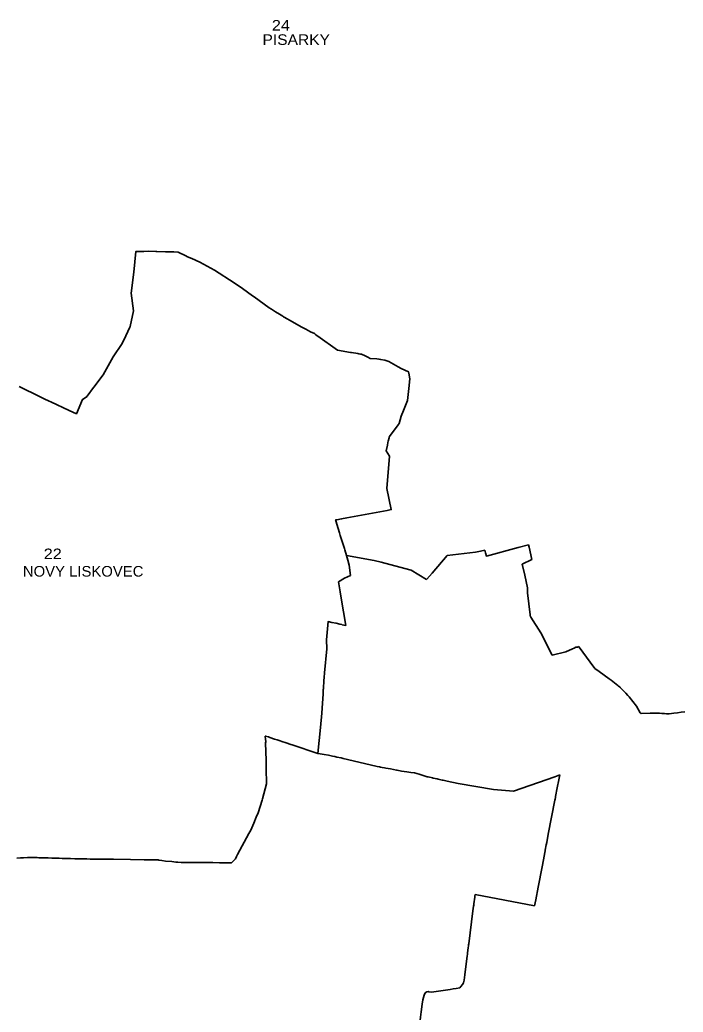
# Model space of a CAD drawing. Extents: x -610940 to -588976, y -1170376 to -1149800.
# Drawn here: x -602206 to -600639, y -1163066 to -1160722 of the extents above; entities that cross this region are included whole.
import ezdxf

# ---------------------------------------------------------------- set-up
doc = ezdxf.new("R2010")
doc.units = 0
doc.header["$LTSCALE"] = 10
doc.layers.add('54', color=7, linetype='Continuous', lineweight=35)
doc.layers.add('55', color=7, linetype='Continuous')
doc.layers.add('56', color=7, linetype='Continuous')

msp = doc.modelspace()

# ---------------------------------------------------------------- linework, layer by layer
at = {"layer": '54'}
for p, q in [((-601028.66, -1161968.5), (-601004.38, -1161961.9)), ((-601004.38, -1161961.9), (-601002.71, -1161967.82)), ((-601433.83, -1161987.17), (-601432.39, -1161993.01)), ((-601433.83, -1161987.17), (-601368.49, -1161999.15)), ((-601232.03, -1162028.94), (-601196.39, -1161987.52)), ((-601196.39, -1161987.52), (-601129.57, -1161979.71)), ((-601129.57, -1161979.71), (-601121.83, -1161978.16)), ((-601121.83, -1161978.16), (-601110.37, -1161975.86)), ((-601110.37, -1161975.86), (-601107.13, -1161975.2)), ((-601002.71, -1161967.82), (-600996.22, -1161996.64)), ((-601368.49, -1161999.15), (-601351.89, -1162003.59)), ((-601351.89, -1162003.59), (-601284.54, -1162021.25)), ((-601018.85, -1162007.88), (-600996.22, -1161996.64)), ((-601018.85, -1162007.88), (-601012.85, -1162033.72)), ((-601012.85, -1162033.72), (-601006.89, -1162063.9)), ((-601453.33, -1162049.5), (-601439.28, -1162040.88)), ((-601453.33, -1162049.5), (-601449.23, -1162073.15)), ((-601006.89, -1162075.78), (-601006.89, -1162063.9)), ((-601006.89, -1162075.78), (-601000.04, -1162127.57)), ((-601458.84, -1162147.68), (-601450.18, -1162149.59)), ((-601450.18, -1162149.59), (-601445.12, -1162150.7)), ((-600998.81, -1162133.13), (-600975.07, -1162170.16)), ((-600975.07, -1162170.16), (-600948.1, -1162222.9)), ((-601481.32, -1162186.65), (-601480.67, -1162207.93)), ((-601486.34, -1162264.83), (-601480.67, -1162207.93)), ((-600948.1, -1162222.9), (-600915.57, -1162215.22)), ((-600915.57, -1162215.22), (-600899.9, -1162207.82)), ((-600899.9, -1162207.82), (-600896.12, -1162206.03)), ((-600896.12, -1162206.03), (-600892.44, -1162204.3)), ((-600892.44, -1162204.3), (-600891.58, -1162203.89)), ((-600891.58, -1162203.89), (-600888.68, -1162203.69)), ((-600858.69, -1162239.36), (-600847.41, -1162254.38)), ((-601487.07, -1162275.64), (-601486.34, -1162264.83)), ((-600847.41, -1162254.38), (-600837.2, -1162261.68)), ((-600837.2, -1162261.68), (-600813.38, -1162278.94)), ((-601487.71, -1162283.88), (-601487.57, -1162281.75)), ((-601487.57, -1162281.75), (-601487.12, -1162276.48)), ((-601487.12, -1162276.48), (-601487.07, -1162275.64)), ((-600813.38, -1162278.94), (-600809.01, -1162282.2)), ((-600809.01, -1162282.2), (-600793.34, -1162294.33)), ((-601488.96, -1162303.8), (-601488.86, -1162302.06)), ((-601488.86, -1162302.06), (-601488.43, -1162295.92)), ((-600793.34, -1162294.33), (-600791.32, -1162295.92)), ((-600791.32, -1162295.92), (-600787.77, -1162298.7)), ((-600778.35, -1162308.57), (-600774.52, -1162312.51)), ((-600774.52, -1162312.51), (-600769.1, -1162318.27)), ((-600769.1, -1162318.27), (-600766.14, -1162321.31)), ((-600766.14, -1162321.31), (-600749.15, -1162343.17)), ((-600749.15, -1162343.17), (-600740.6, -1162359.47)), ((-600740.6, -1162359.47), (-600738.12, -1162360.65)), ((-600738.12, -1162360.65), (-600716.86, -1162360.27)), ((-600716.86, -1162360.27), (-600714.79, -1162360.23)), ((-600714.79, -1162360.23), (-600704.84, -1162360.07)), ((-600698.91, -1162359.97), (-600694.65, -1162360.2)), ((-600694.65, -1162360.2), (-600689.14, -1162360.5)), ((-600689.14, -1162360.5), (-600683.19, -1162360.8)), ((-600683.19, -1162360.8), (-600678.32, -1162361.2)), ((-600678.32, -1162361.2), (-600677.82, -1162361.24)), ((-600677.82, -1162361.24), (-600677.28, -1162361.24)), ((-600677.28, -1162361.24), (-600671.94, -1162361.29)), ((-600671.94, -1162361.29), (-600660.99, -1162359.89)), ((-600660.99, -1162359.89), (-600652.19, -1162358.84)), ((-600652.19, -1162358.84), (-600643.07, -1162357.45)), ((-600643.07, -1162357.45), (-600634.44, -1162356.94)), ((-601501.7, -1162454.97), (-601495.65, -1162394.15)), ((-601501.7, -1162454.97), (-601501.33, -1162455.03)), ((-601501.33, -1162455.03), (-601487.13, -1162457.28)), ((-601487.13, -1162457.28), (-601476.69, -1162458.96)), ((-601476.69, -1162458.96), (-601466.9, -1162461.43)), ((-601456.9, -1162463.71), (-601447.16, -1162465.82)), ((-601447.16, -1162465.82), (-601441.96, -1162467.24)), ((-601441.96, -1162467.24), (-601432.16, -1162469.53)), ((-601432.16, -1162469.53), (-601361.83, -1162485.53)), ((-601361.83, -1162485.53), (-601355.93, -1162486.87)), ((-601355.93, -1162486.87), (-601353.55, -1162487.41)), ((-601353.55, -1162487.41), (-601350.04, -1162488.07)), ((-601350.04, -1162488.07), (-601344.2, -1162489.18)), ((-601344.2, -1162489.18), (-601341.27, -1162489.73)), ((-601341.27, -1162489.73), (-601335.42, -1162490.84)), ((-601335.42, -1162490.84), (-601330.49, -1162491.77)), ((-601330.49, -1162491.77), (-601315.74, -1162494.55)), ((-601315.74, -1162494.55), (-601314.66, -1162494.76)), ((-601314.66, -1162494.76), (-601304.28, -1162496.72)), ((-601304.28, -1162496.72), (-601298.24, -1162497.86)), ((-601282.32, -1162500.25), (-601273.59, -1162500.9)), ((-601273.59, -1162500.9), (-601262.76, -1162504.27)), ((-601262.76, -1162504.27), (-601243.8, -1162510.18)), ((-601243.8, -1162510.18), (-601243.25, -1162510.3)), ((-601231.38, -1162512.82), (-601229.68, -1162513.18)), ((-601229.68, -1162513.18), (-601219.61, -1162515.32)), ((-601207.83, -1162517.82), (-601206.15, -1162518.18)), ((-601206.15, -1162518.18), (-601196.04, -1162520.33)), ((-601196.04, -1162520.33), (-601170.43, -1162525.77)), ((-601170.43, -1162525.77), (-601086.67, -1162540.31)), ((-601039.44, -1162543.83), (-600942.32, -1162509.97)), ((-600942.32, -1162509.97), (-600930.37, -1162505.81)), ((-600937.01, -1162540.25), (-600931.89, -1162513.68)), ((-600931.89, -1162513.68), (-600930.37, -1162505.81)), ((-601086.67, -1162540.31), (-601039.44, -1162543.83)), ((-600939.41, -1162552.68), (-600937.01, -1162540.25)), ((-600957.36, -1162645.8), (-600941.92, -1162565.73)), ((-600961.18, -1162665.65), (-600957.36, -1162645.8)), ((-600972.93, -1162726.75), (-600968.28, -1162702.57)), ((-601130.23, -1162788.42), (-600989.99, -1162815.42)), ((-600989.99, -1162815.42), (-600987.22, -1162801.04)), ((-601233.66, -1163018.61), (-601189.51, -1163012.35)), ((-601189.51, -1163012.35), (-601181.92, -1163011.25)), ((-601181.92, -1163011.25), (-601174.92, -1163010.23)), ((-601174.92, -1163010.23), (-601166.16, -1163008.95)), ((-601159.97, -1163000.61), (-601157.4, -1162997.15)), ((-601253.49, -1163037.24), (-601250.96, -1163025.94)), ((-601250.96, -1163025.94), (-601248.56, -1163020.83))]:
    msp.add_line(p, q, dxfattribs=at)
for points in [[(-602207.92, -1161588.29), (-602157.72, -1161612.88), (-602156.19, -1161613.61), (-602156.09, -1161613.65), (-602150.32, -1161616.24), (-602148.44, -1161617.03), (-602136.35, -1161622.69), (-602132.62, -1161624.45), (-602089.31, -1161645.06), (-602072.21, -1161652.44), (-602057.93, -1161618.76), (-602047.14, -1161612.22), (-602046.68, -1161611.16), (-602031.72, -1161590.66), (-602031.33, -1161590.12), (-602031.25, -1161590.01), (-602009.34, -1161560.33), (-601985.6, -1161518.08), (-601964.4, -1161486.3), (-601955.79, -1161468.6), (-601945.75, -1161447.94), (-601945.57, -1161446.99), (-601945.53, -1161446.77), (-601937.36, -1161409.64), (-601943.18, -1161367.9), (-601936.67, -1161318.18), (-601931.71, -1161269.31), (-601912.9, -1161268.97), (-601902.05, -1161268.79), (-601884.94, -1161269.12), (-601882.17, -1161269.17), (-601861.95, -1161270.06), (-601842.02, -1161270.45), (-601831.78, -1161271.09)], [(-601831.78, -1161271.09), (-601830.11, -1161271.9), (-601815.06, -1161279.1), (-601813.93, -1161279.59), (-601809.93, -1161281.56), (-601799.99, -1161286.06), (-601780.44, -1161294.85), (-601746.12, -1161313.59), (-601699.7, -1161343.16), (-601680.2, -1161357.11), (-601655.94, -1161374.32), (-601652.71, -1161376.64), (-601616.74, -1161402.19), (-601611.54, -1161405.89), (-601602.28, -1161411.53), (-601592.53, -1161417.39), (-601584.23, -1161422.49), (-601582.77, -1161423.42), (-601581.4, -1161424.23), (-601561.42, -1161435.47), (-601540.98, -1161447.06), (-601536.83, -1161449.3), (-601530.63, -1161452.74), (-601519.34, -1161459.01), (-601510.19, -1161463.31), (-601508.37, -1161464.61), (-601507.04, -1161465.54), (-601503.21, -1161468.26), (-601501.78, -1161469.34), (-601455.27, -1161502.72), (-601424.88, -1161507.61), (-601422.42, -1161508.1), (-601407.07, -1161510.51), (-601405.42, -1161510.82), (-601400.81, -1161511.62), (-601398.8, -1161511.92), (-601389.92, -1161516.06), (-601385.23, -1161518.35), (-601383.75, -1161519.06), (-601378.54, -1161521.82)], [(-601378.54, -1161521.82), (-601362.27, -1161522.85), (-601357.62, -1161523.54), (-601353.85, -1161524.18), (-601343.64, -1161526.28), (-601334.29, -1161528.96), (-601312.25, -1161541.69), (-601304.79, -1161545.57), (-601287.79, -1161553.57), (-601287.19, -1161556.38), (-601284.37, -1161570.39), (-601286.98, -1161593.14), (-601290.03, -1161621.68), (-601299.2, -1161644.98), (-601304.68, -1161658.68), (-601309.97, -1161675.9), (-601312.29, -1161678.93), (-601332.98, -1161706.12), (-601333.36, -1161708.22), (-601333.76, -1161709.76), (-601335.47, -1161717.03), (-601336.24, -1161720.4), (-601337.67, -1161726.95), (-601340.66, -1161739.92), (-601332.9, -1161752.66), (-601338.51, -1161829.12), (-601328.64, -1161879.1), (-601337.97, -1161880.83), (-601433.67, -1161898.68), (-601445.94, -1161900.98), (-601456.74, -1161902.97), (-601458.59, -1161903.38), (-601459.55, -1161903.53), (-601460.07, -1161903.6), (-601459.75, -1161905.07), (-601459.47, -1161905.88), (-601458.73, -1161907.99), (-601454.59, -1161921.49), (-601453.82, -1161924.03), (-601450.58, -1161934.14)], [(-601450.58, -1161934.14), (-601449.8, -1161936.82), (-601448.84, -1161940.1), (-601448.04, -1161942.23), (-601439.01, -1161971.06), (-601438, -1161974.42), (-601433.83, -1161987.17)], [(-601107.13, -1161975.2), (-601105.9, -1161980.84), (-601103.68, -1161988.88), (-601028.66, -1161968.5)], [(-601432.39, -1161993.01), (-601430.98, -1161998.7), (-601428.19, -1162010), (-601424.73, -1162034.89)], [(-601284.54, -1162021.25), (-601281.53, -1162022.04), (-601244.9, -1162043.88)], [(-601244.9, -1162043.88), (-601244.21, -1162043.08), (-601232.03, -1162028.94)], [(-601439.28, -1162040.88), (-601439.09, -1162040.82), (-601424.73, -1162034.89)], [(-601449.23, -1162073.15), (-601446.66, -1162088.41), (-601435.6, -1162152.74)], [(-601000.04, -1162127.57), (-600999.94, -1162128.26), (-600999.43, -1162132.15), (-600998.81, -1162133.13)], [(-601481.32, -1162186.65), (-601477.84, -1162143.49), (-601468.71, -1162145.5), (-601458.84, -1162147.68)], [(-601445.12, -1162150.7), (-601444.12, -1162150.92), (-601440.49, -1162151.69), (-601435.6, -1162152.74)], [(-600888.68, -1162203.69), (-600886.99, -1162203.57), (-600885.48, -1162202.29)], [(-600885.48, -1162202.29), (-600884.19, -1162204.04), (-600858.69, -1162239.36)], [(-601488.43, -1162295.92), (-601487.92, -1162288.3), (-601487.71, -1162283.88)], [(-601495.65, -1162394.15), (-601492.65, -1162359.77), (-601490.61, -1162336.49), (-601489.61, -1162315.31), (-601489.01, -1162304.59), (-601488.96, -1162303.8)], [(-600787.77, -1162298.7), (-600787.35, -1162299.03), (-600785.92, -1162300.7), (-600778.35, -1162308.57)], [(-600704.84, -1162360.07), (-600702.86, -1162360.04), (-600698.91, -1162359.97)], [(-601626.68, -1162414.11), (-601625.08, -1162427.52), (-601625.23, -1162429.76), (-601624.25, -1162471.51), (-601623.79, -1162490.32), (-601622.98, -1162526.97), (-601632.79, -1162562.14), (-601633.59, -1162565.55), (-601643.1, -1162595.08), (-601647.77, -1162605.98), (-601653.52, -1162620.04), (-601660.45, -1162636.16), (-601664.71, -1162644.39), (-601691.4, -1162694.06), (-601693.87, -1162698.71), (-601696.45, -1162703.68), (-601705.93, -1162713.25), (-601734.4, -1162713.1), (-601750.2, -1162713.01), (-601754.81, -1162712.98), (-601770.28, -1162712.9), (-601793.81, -1162712.95), (-601800.47, -1162712.84), (-601804.95, -1162712.77), (-601824.45, -1162712.44), (-601833.09, -1162712.3), (-601837.61, -1162711.56), (-601846.49, -1162710.11), (-601862.15, -1162709.44), (-601870.22, -1162707.99), (-601877.72, -1162706.84), (-601879.52, -1162706.56), (-601897.34, -1162706.12), (-601899.09, -1162706.08), (-601912.44, -1162706.16), (-601944.44, -1162705.77), (-601984.47, -1162705.19), (-601987.51, -1162705.15), (-601991.67, -1162705.08), (-601992.56, -1162705.07)], [(-601501.7, -1162454.97), (-601562.8, -1162434.73), (-601565.47, -1162433.82), (-601576.58, -1162430.16), (-601586.93, -1162426.72), (-601591.24, -1162425.29), (-601597.75, -1162423.13), (-601604.01, -1162421.05), (-601615.41, -1162417.26), (-601618.66, -1162416.18), (-601625.4, -1162413.9), (-601626.68, -1162414.11)], [(-601466.9, -1162461.43), (-601461.93, -1162462.47), (-601456.9, -1162463.71)], [(-601298.24, -1162497.86), (-601291.92, -1162498.81), (-601282.32, -1162500.25)], [(-601243.25, -1162510.3), (-601241.5, -1162510.67), (-601231.38, -1162512.82)], [(-601219.61, -1162515.32), (-601217.91, -1162515.68), (-601207.83, -1162517.82)], [(-600941.92, -1162565.73), (-600941.43, -1162563.17), (-600940.6, -1162558.88), (-600940.24, -1162557), (-600939.41, -1162552.68)], [(-600964.95, -1162685.28), (-600964.58, -1162683.36), (-600962.21, -1162671.01), (-600961.18, -1162665.65)], [(-600968.28, -1162702.57), (-600968.08, -1162701.56), (-600964.95, -1162685.28)], [(-601992.56, -1162705.07), (-602020.07, -1162704.66), (-602025.05, -1162704.78), (-602036.41, -1162704.49), (-602039.67, -1162704.44), (-602048.02, -1162704.3), (-602050.37, -1162704.26), (-602054.59, -1162704.19), (-602059.97, -1162704.1), (-602066.53, -1162704), (-602067.86, -1162703.97), (-602070.67, -1162703.92), (-602075.89, -1162703.81), (-602086.12, -1162703.61), (-602091.54, -1162703.52), (-602099.41, -1162703.34), (-602100.01, -1162703.33), (-602105.77, -1162703.04), (-602113.46, -1162702.8), (-602120.27, -1162702.59), (-602130.8, -1162702.26), (-602138.87, -1162702.01), (-602146.9, -1162701.76), (-602152.69, -1162701.58), (-602161.28, -1162701.31), (-602164.67, -1162701.21), (-602170.58, -1162701.02), (-602175.84, -1162700.86), (-602181.86, -1162700.68), (-602187.69, -1162700.5), (-602197.67, -1162701.28), (-602204.18, -1162701.83), (-602213.34, -1162702.56)], [(-600981.47, -1162771.15), (-600980.71, -1162767.21), (-600972.93, -1162726.75)], [(-600987.22, -1162801.04), (-600987.13, -1162800.55), (-600981.47, -1162771.15)], [(-601135.36, -1162826.62), (-601133.95, -1162815.56), (-601133.65, -1162813.22), (-601133.36, -1162810.93), (-601133.26, -1162810.18), (-601131.24, -1162794.88)], [(-601131.24, -1162794.88), (-601131.16, -1162794.31), (-601131.09, -1162793.78), (-601130.74, -1162791.58), (-601130.23, -1162788.42)], [(-601146.06, -1162910.23), (-601145.61, -1162906.8), (-601145.34, -1162904.68), (-601135.36, -1162826.62)], [(-601149.09, -1162933.47), (-601148.62, -1162929.85), (-601148.2, -1162926.6), (-601146.5, -1162913.55), (-601146.06, -1162910.23)], [(-601157.4, -1162997.15), (-601156.54, -1162990.52), (-601154.87, -1162977.77), (-601149.09, -1162933.47)], [(-601248.56, -1163020.83), (-601244.55, -1163018.02), (-601241.45, -1163017.54)], [(-601241.45, -1163017.54), (-601239.64, -1163018.02), (-601233.66, -1163018.61)], [(-601166.16, -1163008.95), (-601163.91, -1163005.91), (-601159.97, -1163000.61)], [(-601257.56, -1163065.29), (-601255.32, -1163047.7), (-601253.49, -1163037.24)], [(-601262.28, -1163105.48), (-601260.6, -1163091.33), (-601259, -1163077.86), (-601257.56, -1163065.29)]]:
    msp.add_lwpolyline(points, dxfattribs=at)

# ---------------------------------------------------------------- texts
at = {"layer": '55'}
for s, width, p in [('PISARKY ', 1.1, (-601632.67, -1160781.29)), ('NOVY LISKOVEC', 1.05, (-602198.81, -1162037.3))]:
    msp.add_text(s, height=25, dxfattribs=dict(at, width=width)).set_placement(p)
at = {"layer": '56', "width": 1.15}
for s, p in [('24 ', (-601610.56, -1160747.5)), ('22 ', (-602149.65, -1161996.1))]:
    msp.add_text(s, height=25, dxfattribs=at).set_placement(p)

doc.saveas('drawing.dxf')
